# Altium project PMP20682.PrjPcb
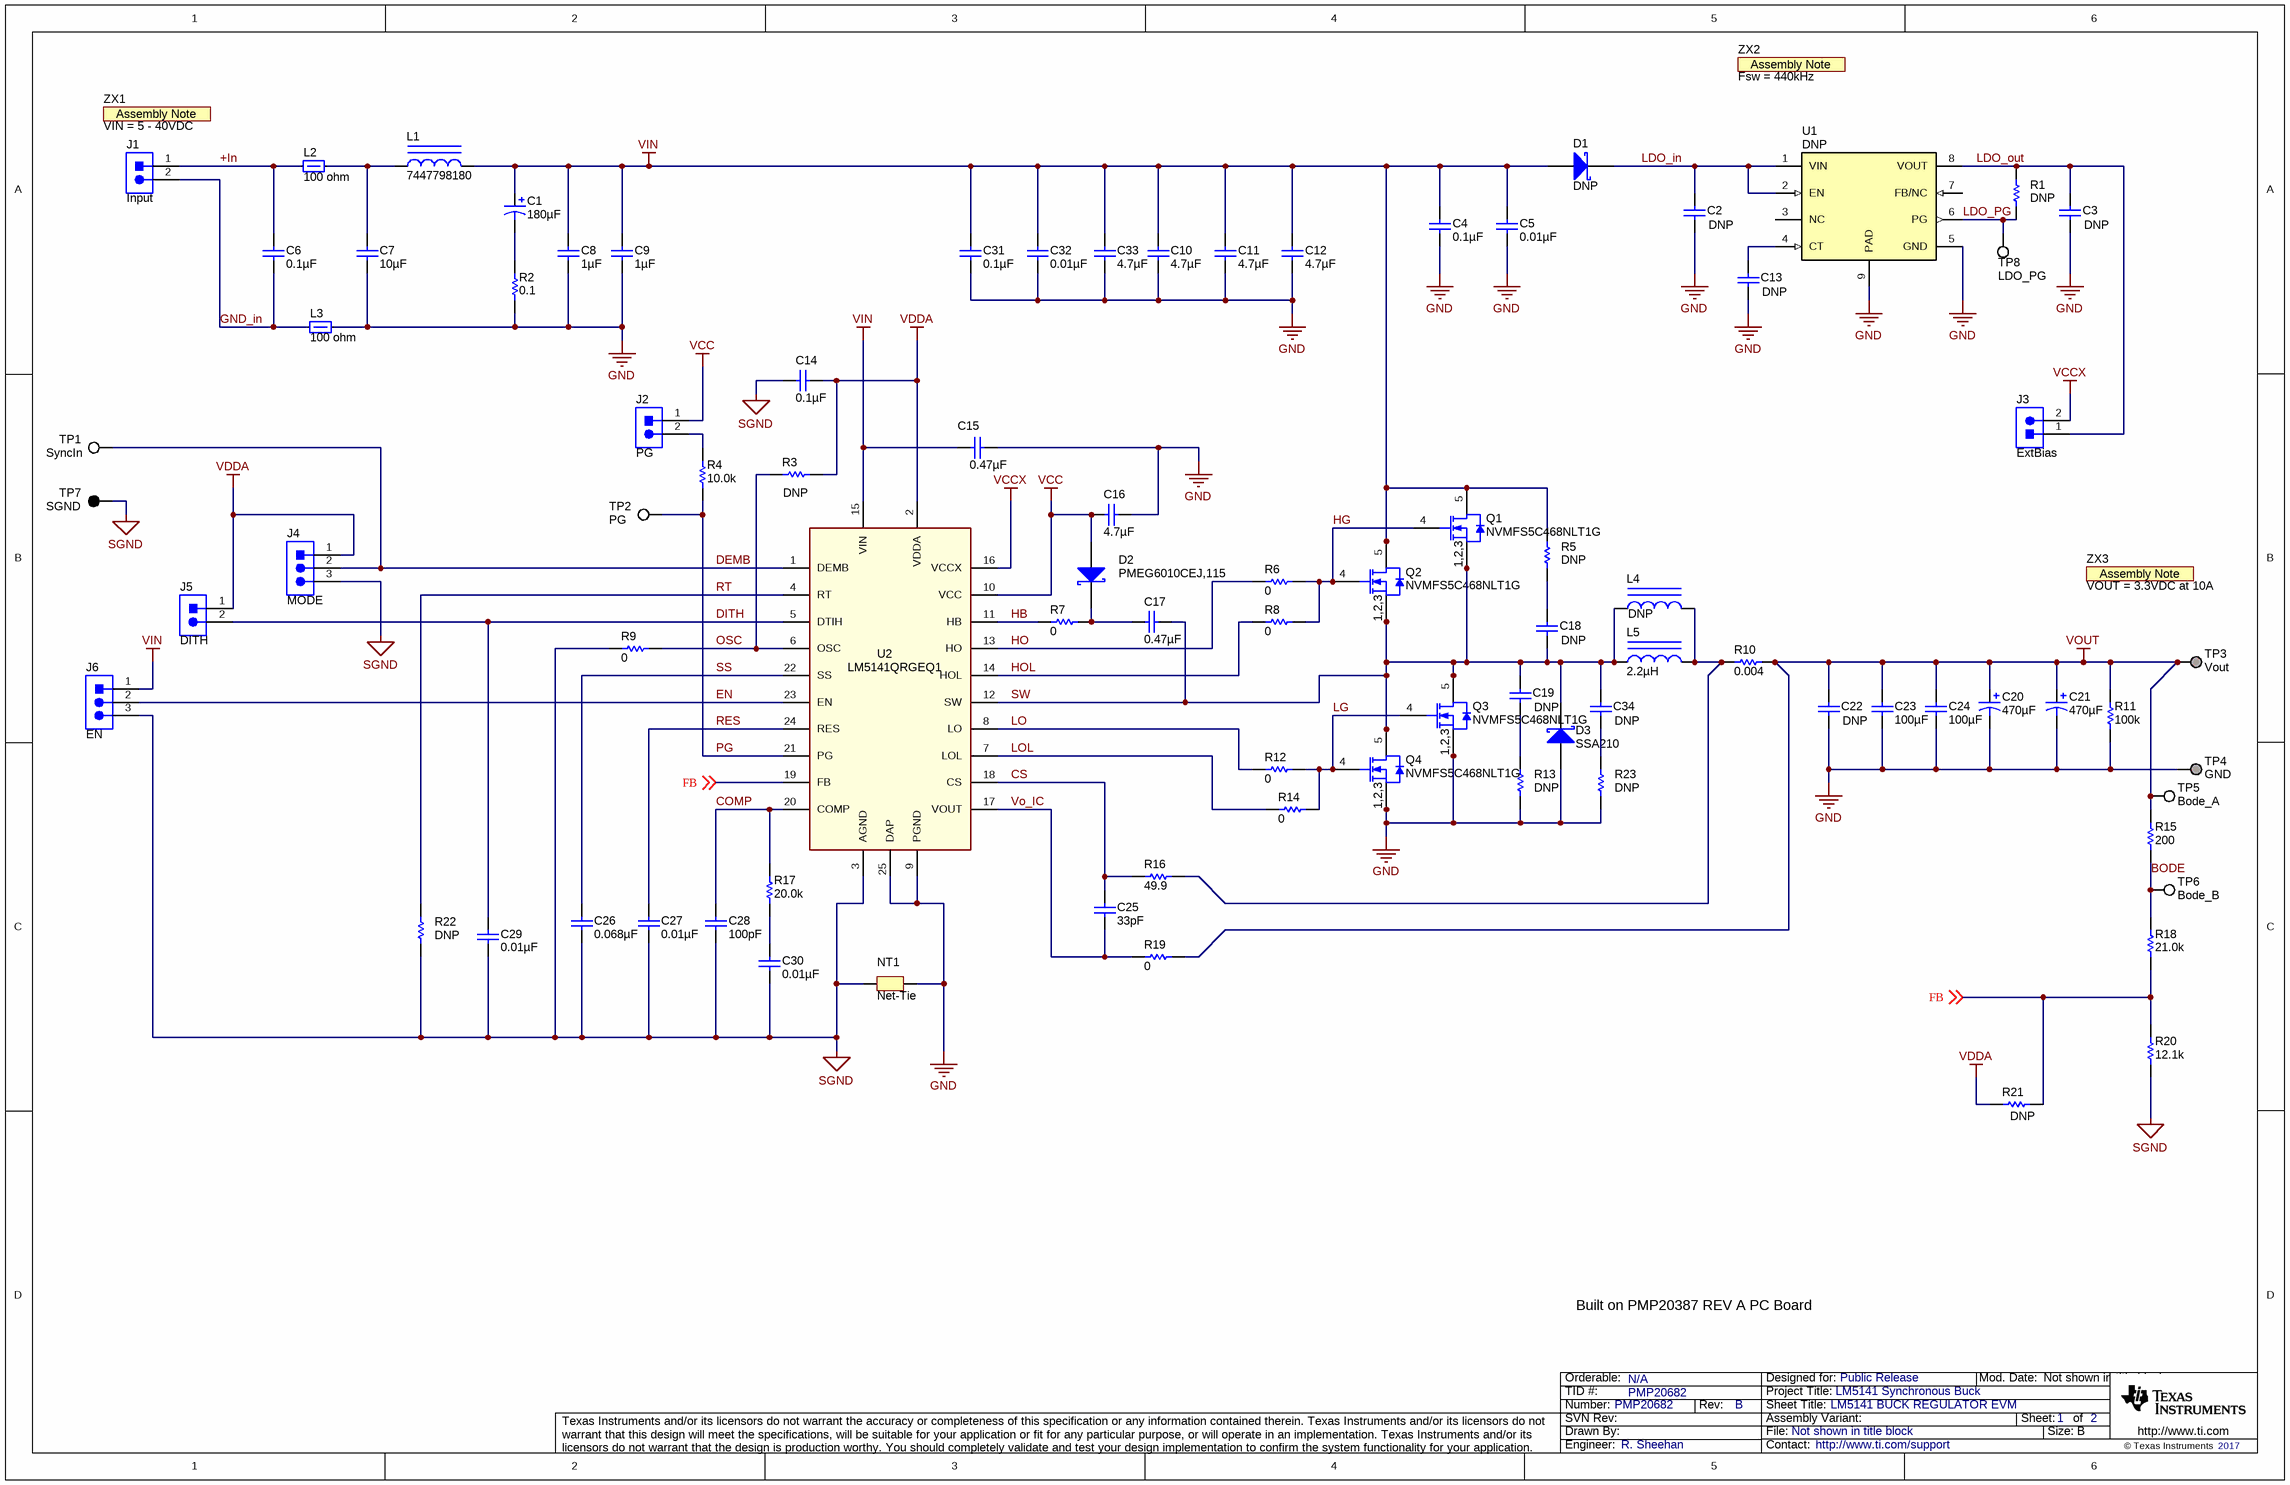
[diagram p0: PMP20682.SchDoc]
CopyrightYear: 2017; EVM_Orderable: N/A; PCB_Layout: H. Kasparian; PCB_Rev: A; PRJ_Customer: Public Release; PRJ_Engineer: R. Sheehan; PRJ_Number: PMP20682; PRJ_Title: LM5141 Synchronous Buck; SCH_Rev: B; TechSupport: http://www.ti.com/support; TID: PMP20682
2 sheets, 120 parts. Net scope: global (net labels, ports and power ports of the same name join across sheets).
Board file: PMP20387.PcbDoc
Sheets:
  PMP20682.SchDoc
  PMP20682-HW.SchDoc

## Sheet PMP20682.SchDoc: LM5141 BUCK REGULATOR EVM
size 431 x 279 mm; Date: Not shown in title block; ApprovedBy: Not shown in title block; CheckedBy: Not shown in title block; Author: Not shown in title block; CompanyName: Not shown in title block; Engineer: Not shown in title block; Organization: Not shown in title block; Address1: Not shown in title block; Address2: Not shown in title block; Address3: Not shown in title block; Address4: Not shown in title block; DocumentNumber: 1; Revision: Use project parameter SCH_Rev; SheetNumber: 1; SheetTotal: 2; PageSetup: Record=PageOptions¦CenterHorizontal=True¦CenterVertical=True¦PrintScale=0.96¦XCorrection=1.00¦YCorrection=1.00¦PrintKind=0¦BorderSize=5000000¦LeftOffset=0¦BottomOffset=0¦Orientation=2¦PaperLength=1000¦PaperWidth=1000¦Scale=100¦PaperSource=15¦PrintQuality=-3¦MediaType=1¦DitherType=10¦PrintScaleMode=1¦PaperKind=11x17¦PaperIndex=17

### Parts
C1  ValueDisplayed: 180µF  [UCZ_1250x1350]  (hidden comment: UCZ1J181MNQ1MS)
C2  DNP  [1206L]
C3  DNP  [0603]
C4  ValueDisplayed: 0.1µF  [0805_HV]  (hidden comment: C0805C104K1RACTU)
C5  ValueDisplayed: 0.01µF  [0603]  (hidden comment: C1608X7R2A103M)
C6  ValueDisplayed: 0.1µF  [0805_HV]  (hidden comment: C0805C104K1RACTU)
C7  ValueDisplayed: 10µF  [1210_280]  (hidden comment: C3225X7R1H106M250AC)
C8  ValueDisplayed: 1µF  [1206L]  (hidden comment: C3216X7R2A105M160AA)
C9  ValueDisplayed: 1µF  [1206L]  (hidden comment: C3216X7R2A105M160AA)
C10  ValueDisplayed: 4.7µF  [1206_190]  (hidden comment: UMK316AB7475KL-T)
C11  ValueDisplayed: 4.7µF  [1206_190]  (hidden comment: UMK316AB7475KL-T)
C12  ValueDisplayed: 4.7µF  [1206_190]  (hidden comment: UMK316AB7475KL-T)
C13  DNP  [0603]
C14  ValueDisplayed: 0.1µF  [0603]  (hidden comment: C0603C104K5RACTU)
C15  ValueDisplayed: 0.47µF  [0805L]  (hidden comment: GRM21BR72A474KA73L)
C16  ValueDisplayed: 4.7µF  [0603]  (hidden comment: GRM188R61C475KAAJ)
C17  ValueDisplayed: 0.47µF  [0603]  (hidden comment: CGA3E3X7R1H474K080AB)
C18  DNP  [0603]
C19  DNP  [0603]
C20  ValueDisplayed: 470µF  [CAPSMT_62_JC0]  (hidden comment: 16SVPE470M)
C21  ValueDisplayed: 470µF  [CAPSMT_62_JC0]  (hidden comment: 16SVPE470M)
C22  DNP  [0603]
C23  ValueDisplayed: 100µF  [1210_280]  (hidden comment: LMK325ABJ107MMHT)
C24  ValueDisplayed: 100µF  [1210_280]  (hidden comment: LMK325ABJ107MMHT)
C25  ValueDisplayed: 33pF  [0603]  (hidden comment: 06035A330JAT2A)
C26  ValueDisplayed: 0.068µF  [0603]  (hidden comment: GRM188R71E683KA01D)
C27  ValueDisplayed: 0.01µF  [0603]  (hidden comment: C1608X7R2A103M)
C28  ValueDisplayed: 100pF  [0603]  (hidden comment: GRM1885C1H101JA01D)
C29  ValueDisplayed: 0.01µF  [0603]  (hidden comment: C1608X7R2A103M)
C30  ValueDisplayed: 0.01µF  [0603]  (hidden comment: GRM188R71E103KA01D)
C31  ValueDisplayed: 0.1µF  [0805_HV]  (hidden comment: C0805C104K1RACTU)
C32  ValueDisplayed: 0.01µF  [0603]  (hidden comment: C1608X7R2A103M)
C33  ValueDisplayed: 4.7µF  [1206_190]  (hidden comment: UMK316AB7475KL-T)
C34  DNP  [0603]
D1  DNP  [SOD-323F]
D2  PMEG6010CEJ,115  [SOD-323F]
D3  SSA210  [SMA]
J1  Input  [Phoenix_1729018]
J2  PG  [WURTH_61300211121]
J3  ExtBias  [WURTH_61300211121]
J4  MODE  [WURTH_61300311121]
J5  DITH  [WURTH_61300211121]
J6  EN  [WURTH_61300311121]
L1  7447798180  [WE-PDF_1064]
L2  value 100 ohm  [WE-MPSB_2220_1800]  (hidden comment: 74279224101)
L3  value 100 ohm  [WE-MPSB_2220_1800]  (hidden comment: 74279224101)
L4  DNP  [IHLP-4040DZ]
L5  ValueDisplayed: 2.2µH  [XAL1060]  (hidden comment: XAL1060-222MEB)
NT1  Net-Tie  [Net-Tie_10mil]  (net tie, no BOM)
Q1  NVMFS5C468NLT1G  [TRANS_DFN5]
Q2  NVMFS5C468NLT1G  [TRANS_DFN5]
Q3  NVMFS5C468NLT1G  [TRANS_DFN5]
Q4  NVMFS5C468NLT1G  [TRANS_DFN5]
R1  DNP  [0603]
R2  ValueDisplayed: 0.1  [2010]  (hidden comment: WSL2010R1000FEA)
R3  DNP  [0603]
R4  ValueDisplayed: 10.0k  [0603]  (hidden comment: CRCW060310K0FKEA)
R5  DNP  [1206]
R6  ValueDisplayed: 0  [0603S]  (hidden comment: CRCW06030000Z0EA)
R7  ValueDisplayed: 0  [0603S]  (hidden comment: CRCW06030000Z0EA)
R8  ValueDisplayed: 0  [0603S]  (hidden comment: CRCW06030000Z0EA)
R9  ValueDisplayed: 0  [0603]  (hidden comment: CRCW06030000Z0EA)
R10  ValueDisplayed: 0.004  [2512_WIDE]  (hidden comment: KRL6432E-M-R004-F-T1)
R11  ValueDisplayed: 100k  [0603]  (hidden comment: CRCW0603100KFKEA)
R12  ValueDisplayed: 0  [0603S]  (hidden comment: CRCW06030000Z0EA)
R13  DNP  [1206]
R14  ValueDisplayed: 0  [0603S]  (hidden comment: CRCW06030000Z0EA)
R15  ValueDisplayed: 200  [0603]  (hidden comment: CRCW0603200RFKEA)
R16  ValueDisplayed: 49.9  [0603]  (hidden comment: CRCW060349R9FKEA)
R17  ValueDisplayed: 20.0k  [0603]  (hidden comment: CRCW060320K0FKEA)
R18  ValueDisplayed: 21.0k  [0603]  (hidden comment: CRCW060321K0FKEA)
R19  ValueDisplayed: 0  [0603]  (hidden comment: CRCW06030000Z0EA)
R20  ValueDisplayed: 12.1k  [0603]  (hidden comment: CRCW060312K1FKEA)
R21  DNP  [0603]
R22  DNP  [0603]
R23  DNP  [1206]
TP1  SyncIn  [Keystone5012]
TP2  PG  [Keystone5002]
TP3  Vout  [Keystone1598-2]
TP4  GND  [Keystone1598-2]
TP5  Bode_A  [Keystone5012]
TP6  Bode_B  [Keystone5012]
TP7  SGND  [Keystone5011]
TP8  LDO_PG  [Keystone5012]
U1  DNP  [DGN0008D_N]
U2  LM5141QRGEQ1  [RGE0024H]
ZX1  VIN = 5 - 40VDC  [AssemblyNote]  (no BOM)
ZX2  Fsw = 440kHz  [AssemblyNote]  (no BOM)
ZX3  VOUT = 3.3VDC at 10A  [AssemblyNote]  (no BOM)

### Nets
GND: C2.2 C3.2 C4.2 C5.2 C7.2 C8.2 C9.2 C10.2 C11.2 C12.2 C13.2 C15.1 C16.1 C20.2(-) C21.2(-) C22.2 C23.2 C24.2 C31.2 C32.2 C33.2 D3.2(A) L3.2 NT1.2 Q3.1(S) Q3.2(S) Q3.3(S) Q4.1(S) Q4.2(S) Q4.3(S) R2.1 R11.1 R13.1 R23.1 TP4.1 U1.5(GND) U1.9(PAD) U2.9(PGND) U2.25(DAP)
SGND: C14.1 C26.2 C27.2 C28.2 C29.2 C30.2 J4.3 J6.3 NT1.1 R9.2 R20.1 R22.1 TP7.1 U2.3(AGND)
VCC: C16.2 D2.2(A) J2.1 U2.10(VCC)
VCCX: J3.2 U2.16(VCCX)
VDDA: C14.2 J4.1 J5.1 R3.1 R21.1 U2.2(VDDA)
VIN: C1.1(+) C4.1 C5.1 C8.1 C9.1 C10.1 C11.1 C12.1 C15.2 C31.1 C32.1 C33.1 D1.2(A) J6.1 L1.2 Q1.5(D) Q1.6(D) Q2.5(D) Q2.6(D) R5.2 U2.15(VIN)
VOUT: C20.1(+) C21.1(+) C22.1 C23.1 C24.1 R10.2 R11.2 R15.2 R19.2 TP3.1 TP5.1
+In: C6.1 J1.1 L2.1
BODE: R15.1 R18.2 TP6.1
COMP: C28.1 R17.2 U2.20(COMP)
CS: C25.2 R16.1 U2.18(CS)
DEMB: J4.2 TP1.1 U2.1(DEMB)
DITH: C29.1 J5.2 U2.5(DTIH)
EN: J6.2 U2.23(EN)
FB: R18.1 R20.2 R21.2 U2.19(FB) ; off-sheet FB
GND_in: C6.2 J1.2 L3.1
HB: R7.1 U2.11(HB)
HG: Q1.4(G) Q2.4(G) R6.2 R8.1
HO: R6.1 U2.13(HO)
HOL: R8.2 U2.14(HOL)
LDO_in: C2.1 D1.1(K) U1.1(VIN) U1.2(EN)
LDO_out: C3.1 J3.1 R1.2 U1.8(VOUT)
LDO_PG: R1.1 TP8.1 U1.6(PG)
LG: Q3.4(G) Q4.4(G) R12.2 R14.1
LO: R12.1 U2.8(LO)
LOL: R14.2 U2.7(LOL)
OSC: R3.2 R9.1 U2.6(OSC)
PG: R4.2 TP2.1 U2.21(PG)
RES: C27.1 U2.24(RES)
RT: R22.2 U2.4(RT)
SS: C26.1 U2.22(SS)
SW: C17.2 C18.2 C19.1 C34.1 D3.1(K) L4.1 L5.1 Q1.1(S) Q1.2(S) Q1.3(S) Q2.1(S) Q2.2(S) Q2.3(S) Q3.5(D) Q3.6(D) Q4.5(D) Q4.6(D) U2.12(SW)
Vo_IC: C25.1 R19.1 U2.17(VOUT)
NetC1_2: C1.2(-) R2.2
NetC7_1: C7.1 L1.1 L2.2
NetC13_1: C13.1 U1.4(CT)
NetC17_1: C17.1 D2.1(K) R7.2
NetC18_1: C18.1 R5.1
NetC19_2: C19.2 R13.2
NetC30_1: C30.1 R17.1
NetC34_2: C34.2 R23.2
NetJ2_2: J2.2 R4.1
NetL4_2: L4.2 L5.2 R10.1 R16.2

Not connected (* = marked no-connect by the designer): U1 3(NC) 7(FB/NC)

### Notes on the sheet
- Built on PMP20387 REV A PC Board

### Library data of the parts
C1 = UCZ1J181MNQ1MS: CAP, AL, 180 µF, 63 V, +/- 20%, 0.2 ohm, AEC-Q200 Grade 1, SMD; Manufacturer: Nichicon; Polarized: Y; CompType: Capacitor; Value: 180uF; U/M: EA; Cap_F: 0.00018; Tolerance_%: 20; Value1: 0.2 ohm; VDC_V: 63; Value2: 63V; ESR_ohm: 0.2; IRMS_A: 1; TaMin_C: -40; TaMax_C: 125; Cap_Case: 12.5x13.5mm; AEC Category: Q200
C2 = C3216X7R2A105M160AA: CAP, CERM, 1 µF, 100 V, +/- 20%, X7R, 1206; Manufacturer: TDK; Polarized: N; CompType: Capacitor; Value: 1uF; ValueDisplayed: 1µF; U/M: EA; Cap_F: 0.000001; Tolerance_%: 20; Value1: Unknown; VDC_V: 100; Value2: 100V; TaMin_C: -55; TaMax_C: 125; Cap_Case: 1206
C3 = GRM188Z71C225KE43: CAP, CERM, 2.2 µF, 16 V, +/- 10%, X7R, 0603; Manufacturer: MuRata; Polarized: N; CompType: Capacitor; Value: 2.2uF; ValueDisplayed: 2.2µF; U/M: EA; Cap_F: 0.0000022; Tolerance_%: 10; Value1: Unknown; VDC_V: 16; Value2: 16V; TaMin_C: -55; TaMax_C: 125; SizeArea_mm2: 1.28; SizeAreaWB_mm2: 4.68; SizeX_mm: 1.6; SizeY_mm: 0.8; SizeZ_mm: 1; AEC Category: Q200
C4 C6 C31 = C0805C104K1RACTU: CAP, CERM, 0.1 µF, 100 V, +/- 10%, X7R, 0805; Manufacturer: Kemet; Polarized: N; CompType: Capacitor; Value: 0.1uF; U/M: EA; Cap_F: 0.0000001; Tolerance_%: 10; ESR_ohm: 0.064; Value1: 0.064 ohm; VDC_V: 100; Value2: 100V; IRMS_A: 1.64; TaMin_C: -55; TaMax_C: 125; Cap_Case: 0805
C5 C27 C29 C32 = C1608X7R2A103M: CAP, CERM, 0.01 µF, 100 V, +/- 20%, X7R, 0603; Manufacturer: TDK; Polarized: N; CompType: Capacitor; Value: 0.01uF; U/M: EA; Cap_F: 0.00000001; Tolerance_%: 20; ESR_ohm: 0.0661; Value1: 0.0661 ohm; VDC_V: 100; Value2: 100V; TaMin_C: -55; TaMax_C: 125
C7 = C3225X7R1H106M250AC: CAP, CERM, 10 µF, 50 V, +/- 20%, X7R, 1210; Manufacturer: TDK; Polarized: N; CompType: Capacitor; Value: 10uF; U/M: EA; Cap_F: 0.00001; Tolerance_%: 20; Value1: Unknown; VDC_V: 50; Value2: 50V; TaMin_C: -55; TaMax_C: 125; Cap_Case: 1210
C8 C9 = C3216X7R2A105M160AA: CAP, CERM, 1 µF, 100 V, +/- 20%, X7R, 1206; Manufacturer: TDK; Polarized: N; CompType: Capacitor; Value: 1uF; U/M: EA; Cap_F: 0.000001; Tolerance_%: 20; Value1: Unknown; VDC_V: 100; Value2: 100V; TaMin_C: -55; TaMax_C: 125; Cap_Case: 1206
C10-C12 C33 = UMK316AB7475KL-T: CAP, CERM, 4.7 µF, 50 V, +/- 10%, X7R, 1206_190; Manufacturer: Taiyo Yuden; Polarized: N; CompType: Capacitor; Value: 4.7uF; U/M: EA; Cap_F: 0.0000047; Tolerance_%: 10; Value1: Unknown; VDC_V: 50; Value2: 50V; TaMin_C: -55; TaMax_C: 125; Cap_Case: 1206; SizeArea_mm2: 5.12; SizeAreaWB_mm2: 10.92; SizeX_mm: 3.2; SizeY_mm: 1.6; SizeZ_mm: 1.9; AEC Category: Q200
C13 = GRM188R71E102KA01D: CAP, CERM, 1000 pF, 25 V, +/- 10%, X7R, 0603; Manufacturer: MuRata; Polarized: N; CompType: Capacitor; Value: 1000pF; U/M: EA; Cap_F: 0.000000001; Tolerance_%: 10; Value1: Unknown; VDC_V: 25; Value2: 25V; TaMin_C: -55; TaMax_C: 125; SizeArea_mm2: 1.28; SizeAreaWB_mm2: 4.68; SizeX_mm: 1.6; SizeY_mm: 0.8; SizeZ_mm: 1; AEC Category: Q200
C14 = C0603C104K5RACTU: CAP, CERM, 0.1 µF, 50 V, +/- 10%, X7R, 0603; Manufacturer: Kemet; Polarized: N; CompType: Capacitor; Value: 0.1uF; U/M: EA; Cap_F: 0.0000001; Tolerance_%: 10; Value1: Unknown; VDC_V: 50; Value2: 50V; TaMin_C: -55; TaMax_C: 125
C15 = GRM21BR72A474KA73L: CAP, CERM, 0.47 µF, 100 V, +/- 10%, X7R, 0805; Manufacturer: MuRata; Polarized: N; CompType: Capacitor; Value: 0.47uF; U/M: EA; Cap_F: 0.00000047; Tolerance_%: 10; Value1: Unknown; VDC_V: 100; Value2: 100V; TaMin_C: -55; TaMax_C: 125; Cap_Case: 0805
C16 = GRM188R61C475KAAJ: CAP, CERM, 4.7 µF, 16 V, +/- 10%, X5R, 0603; Manufacturer: MuRata; Polarized: N; CompType: Capacitor; Value: 4.7uF; U/M: EA; Cap_F: 0.0000047; Tolerance_%: 10; Value1: Unknown; VDC_V: 16; Value2: 16V; TaMin_C: -55; TaMax_C: 85
C17 = CGA3E3X7R1H474K080AB: CAP, CERM, 0.47 µF, 50 V, +/- 10%, X7R, AEC-Q200 Grade 1, 0603; Manufacturer: TDK; Polarized: N; CompType: Capacitor; Value: 0.47uF; U/M: EA; Cap_F: 0.00000047; Tolerance_%: 10; ESR_ohm: 0.01064; Value1: 0.01064 ohm; VDC_V: 50; Value2: 50V; IRMS_A: 1.59966; TaMin_C: -55; TaMax_C: 125; SizeArea_mm2: 1.28; SizeAreaWB_mm2: 4.68; SizeX_mm: 1.6; SizeY_mm: 0.8; SizeZ_mm: 1; AEC Category: Q200; AEC Qualified: Y
C18 C19 C34 = GRM1885C2A102JA01D: CAP, CERM, 1000 pF, 100 V, +/- 5%, C0G/NP0, 0603; Manufacturer: MuRata; Polarized: N; CompType: Capacitor; Value: 1000pF; U/M: EA; Cap_F: 0.000000001; Tolerance_%: 5; Value1: Unknown; VDC_V: 100; Value2: 100V; TaMin_C: -55; TaMax_C: 125
C20 C21 = 16SVPE470M: CAP, Aluminum Polymer, 470 µF, 16 V, +/- 20%, 0.01 ohm, JC0 SMD; Manufacturer: Panasonic; Polarized: Y; CompType: Capacitor; Value: 470uF; U/M: EA; Cap_F: 0.00047; Tolerance_%: 20; VDC_V: 16; Value2: 16V; ESR_ohm: 0.01; IRMS_A: 6.1; TaMin_C: -55; TaMax_C: 105; AEC Category: Q200; SizeAreaWB_mm2: 156.25; SizeArea_mm2: 110.25; SizeX_mm: 10.5; SizeZ_mm: 12.5
C22 = C0603C104K5RACTU: CAP, CERM, 0.1 µF, 50 V, +/- 10%, X7R, 0603; Manufacturer: Kemet; Polarized: N; CompType: Capacitor; Value: 0.1uF; ValueDisplayed: 0.1µF; U/M: EA; Cap_F: 0.0000001; Tolerance_%: 10; Value1: Unknown; VDC_V: 50; Value2: 50V; TaMin_C: -55; TaMax_C: 125
C23 C24 = LMK325ABJ107MMHT: CAP, CERM, 100 µF, 10 V, +/- 20%, X5R, AEC-Q200 Grade 3, 1210; Manufacturer: Taiyo Yuden; Polarized: N; CompType: Capacitor; Value: 100uF; U/M: EA; Cap_F: 0.0001; Tolerance_%: 20; Value1: Unknown; VDC_V: 10; Value2: 10V; TaMin_C: -55; TaMax_C: 85; Cap_Case: 1210; SizeArea_mm2: 8; SizeAreaWB_mm2: 14.7; SizeX_mm: 3.2; SizeY_mm: 2.5; SizeZ_mm: 2.8; AEC Category: Q200; AEC Qualified: Y; AEC Grade: 3
C25 = 06035A330JAT2A: CAP, CERM, 33 pF, 50 V, +/- 5%, C0G/NP0, 0603; Manufacturer: AVX; Polarized: N; CompType: Capacitor; Value: 33pF; U/M: EA; Cap_F: 0.000000000033; Tolerance_%: 5; ESR_ohm: 0.209; Value1: 0.209 ohm; VDC_V: 50; Value2: 50V; TaMin_C: -55; TaMax_C: 125
C26 = GRM188R71E683KA01D: CAP, CERM, 0.068 µF, 25 V, +/- 10%, X7R, 0603; Manufacturer: MuRata; Polarized: N; CompType: Capacitor; Value: 0.068uF; U/M: EA; Cap_F: 0.000000068; Tolerance_%: 10; Value1: Unknown; VDC_V: 25; Value2: 25V; TaMin_C: -55; TaMax_C: 125
C28 = GRM1885C1H101JA01D: CAP, CERM, 100 pF, 50 V, +/- 5%, C0G/NP0, 0603; Manufacturer: MuRata; Polarized: N; CompType: Capacitor; Value: 100pF; U/M: EA; Cap_F: 0.0000000001; Tolerance_%: 5; Value1: Unknown; VDC_V: 50; Value2: 50V; TaMin_C: -55; TaMax_C: 125; SizeArea_mm2: 1.28; SizeAreaWB_mm2: 4.68; SizeX_mm: 1.6; SizeY_mm: 0.8; SizeZ_mm: 1; AEC Category: Q200
C30 = GRM188R71E103KA01D: CAP, CERM, 0.01 µF, 25 V, +/- 10%, X7R, 0603; Manufacturer: MuRata; Polarized: N; CompType: Capacitor; Value: 0.01uF; U/M: EA; Cap_F: 0.00000001; Tolerance_%: 10; Value1: Unknown; VDC_V: 25; Value2: 25V; TaMin_C: -55; TaMax_C: 125; SizeArea_mm2: 1.28; SizeAreaWB_mm2: 4.68; SizeX_mm: 1.6; SizeY_mm: 0.8; SizeZ_mm: 1; AEC Category: Q200
D1 D2 = PMEG6010CEJ,115: Diode, Schottky, 60 V, 1 A, SOD-323F; Manufacturer: NXP Semiconductor; U/M: EA; Vf_V: 0.66; Value: 60V; Value1: 1A; Value2: 0.66V; Io_A: 1; Vr_V: 60; TJmax_C: 150
D3 = SSA210: Diode, Schottky, 100 V, 2 A, AEC-Q101, SMA; Manufacturer: Fairchild Semiconductor; U/M: EA; Vf_V: 0.8; Value: 100V; Value1: 2A; Value2: 0.8V; Io_A: 2; Vr_V: 100; TJmax_C: 175; SizeAreaWB_mm2: 37.3428; SizeArea_mm2: 16.3228; SizeX_mm: 5.59; SizeY_mm: 2.92; SizeZ_mm: 2.87; AEC Category: Q101; AEC Qualified: Y
J1 = 1729018: TERM BLOCK 2POS 5mm, TH; Manufacturer: Phoenix Contact; SymbolCreator: a0412235; CompType: Header; U/M: EA
J2 J3 J5 = 61300211121: Header, 2.54 mm, 2x1, Gold, TH; Manufacturer: Wurth Elektronik; SymbolCreator: a0412235
J4 J6 = 61300311121: Header, 2.54 mm, 3x1, Gold, TH; Manufacturer: Wurth Elektronik; SymbolCreator: a0799628
L1 = 7447798180: Inductor, Shielded, Metal Composite, 1.8 µH, 12.8 A, 0.0038 ohm, SMD; Manufacturer: Wurth Elektronik; Value: 1.8uH; Ind_H: 1.8E-6; ValueDisplayed: 1.8µH; Imax_A: 12.8; Irms: 14.5A @ 40C rise; Isat: 12.8A @ 10% inductance drop; DCR_ohm: 0.0038; Value2: 12.8A
L2 L3 = 74279224101: Ferrite Bead, 100 ohm @ 100 MHz, 7 A, 2220 (H=1.8mm); Manufacturer: Wurth Elektronik; Imax_A: 7; DCR_ohm: 0.005; Value1: 0.005 ohm; Value2: 7A; ZTyp@100MHz_Ohm: 100
L4 = IHLP4040DZER2R0M11: Inductor, Shielded Drum Core, Powdered Iron, 2 µH, 14 A, 0.0058 ohm, SMD; Manufacturer: Vishay-Dale; Value: 2uH; ValueDisplayed: 2µH; Ind_H: 2.0E-6; Imax_A: 14; Irms: 16A @ 40C rise; Isat: 14A @ 20% inductance drop; DCR_ohm: 0.0058; Value2: 14A; AEC Category: Q200; AEC Qualified: N
L5 = XAL1060-222MEB: Inductor, Shielded, Composite, 2.2 µH, 20 A, 0.0045 ohm, AEC-Q200 Grade 1, SMD; Manufacturer: Coilcraft; Value: 2.2uH; Ind_H: 2.2E-6; Imax_A: 20; Irms: 20A @ 40C rise; Isat: 32A @ 30% inductance drop; DCR_ohm: 0.0045; Value2: 20A; AEC Category: Q200; AEC Qualified: Y; AEC Grade: 1; SizeAreaWB_mm2: 159.6; SizeArea_mm2: 113; SizeX_mm: 11.3; SizeY_mm: 10; SizeZ_mm: 6
NT1 = Net-Tie: Single point connection between nets.; SymbolCreator: codlsc
Q1-Q4 = NVMFS5C468NL: MOSFET, N-CH, 40 V, 37 A, AEC-Q101, DFN5 5x6mm; Manufacturer: ON Semiconductor; Alternate Manufacturer: None; U/M: EA; VdsMax_V: 40; ChType: N; Value: 40V; Value1: 0.0145 ohm; Rdson45_ohm: 0.0145; Value2: 4.5 nC; QgTyp_nC: 4.5; Vgs_V: 20; IdsMax_A: 27; SizeAreaWB_mm2: 58.2725; SizeArea_mm2: 31.6725; SizeX_mm: 5.15; SizeY_mm: 6.15; SizeZ_mm: 1; AEC Category: Q101; AEC Qualified: Y
R1 R4 = CRCW060310K0FKEA: RES, 10.0 k, 1%, 0.1 W, 0603; Manufacturer: Vishay-Dale; CompType: Resistor; Value: 10.0k; Res_ohm: 10000; Value_Code: 10k0; Tolerance_%: 1; Power_W: 0.1; Value2: 0.1W; VDC_V: 75; TempCo: 100 ppm/C; EIA_Code: E96; U/M: EA
R2 = WSL2010R1000FEA: RES, 0.1, 1%, 0.5 W, 2010; Manufacturer: Vishay-Dale; CompType: Resistor; Value: 0.1; Value_Code: R100; Tolerance_%: 1; Power_W: 0.5; Value2: 0.5W; TempCo: 75 ppm/C; EIA_Code: E96; U/M: EA; SizeArea_mm2: 12.5; SizeX_mm: 5; SizeY_mm: 2.5; SizeZ_mm: 1.66; AEC Category: Q200
R3 R8 R9 R19 = CRCW06030000Z0EA: RES, 0, 5%, 0.1 W, 0603; Manufacturer: Vishay-Dale; CompType: Resistor; Value: 0; Value_Code: 0000; Tolerance_%: 5; Power_W: 0.1; Value2: 0.1W; VDC_V: 75; TempCo: 200 ppm/C; EIA_Code: E24; U/M: EA
R5 R13 R23 = CRM1206-JW-1R0ELF: RES, 1.0, 5%, 0.5 W, 1206; Manufacturer: Bourns; CompType: Resistor; Value: 1.0; Res_ohm: 1; Value_Code: 1R00; Tolerance_%: 5; Power_W: 0.5; Value2: 0.5W; TempCo: 150 ppm/C; EIA_Code: E24; U/M: EA
R6 R7 R12 R14 = CRCW06030000Z0EA: RES, 0, 5%, 0.1 W, 0603; Manufacturer: Vishay-Dale; CompType: Resistor; Value: 0; Value_Code: 0000; Tolerance_%: 5; Power_W: 0.1; Value2: 0.1W; VDC_V: 75; TempCo: 200 ppm/C; EIA_Code: E24; U/M: EA; SizeArea_mm2: 1.28; SizeX_mm: 1.6; SizeY_mm: 0.8; SizeZ_mm: 1; AEC Category: Q200
R10 = KRL6432E-M-R007-F-T1: RES, 0.004, 1%, 3 W, 2512 WIDE; Manufacturer: Susumu Co Ltd; CompType: Resistor; Value: 0.004; U/M: EA; Value_Code: 4L000; Tolerance_%: 1; Power_W: 3; Value2: 3W; TempCo: 50 ppm/C; SizeArea_mm2: 20.16; SizeAreaWB_mm2: 43.16; SizeX_mm: 3.2; SizeY_mm: 6.3; SizeZ_mm: 0.7; EIA_Code: E96; AEC Category: Q200
R11 = CRCW0603100KFKEA: RES, 100 k, 1%, 0.1 W, 0603; Manufacturer: Vishay-Dale; CompType: Resistor; Value: 100k; Res_ohm: 100000; Tolerance_%: 1; Power_W: 0.1; Value2: 0.1W; VDC_V: 75; TempCo: 100 ppm/C; EIA_Code: E96; U/M: EA
R15 = CRCW0603200RFKEA: RES, 200, 1%, 0.1 W, 0603; Manufacturer: Vishay-Dale; CompType: Resistor; Value: 200; Value_Code: 200R; Tolerance_%: 1; Power_W: 0.1; Value2: 0.1W; VDC_V: 75; TempCo: 100 ppm/C; EIA_Code: E96; U/M: EA; SizeArea_mm2: 1.28; SizeX_mm: 1.6; SizeY_mm: 0.8; AEC Category: Q200
R16 = CRCW060349R9FKEA: RES, 49.9, 1%, 0.1 W, 0603; Manufacturer: Vishay-Dale; CompType: Resistor; Value: 49.9; Value_Code: 49R9; Tolerance_%: 1; Power_W: 0.1; Value2: 0.1W; VDC_V: 75; TempCo: 100 ppm/C; EIA_Code: E96; U/M: EA
R17 = CRCW060320K0FKEA: RES, 20.0 k, 1%, 0.1 W, 0603; Manufacturer: Vishay-Dale; CompType: Resistor; Value: 20.0k; Res_ohm: 20000; Value_Code: 20k0; Tolerance_%: 1; Power_W: 0.1; Value2: 0.1W; VDC_V: 75; TempCo: 100 ppm/C; EIA_Code: E96; U/M: EA; SizeArea_mm2: 1.28; SizeX_mm: 1.6; SizeY_mm: 0.8; AEC Category: Q200
R18 = CRCW060321K0FKEA: RES, 21.0 k, 1%, 0.1 W, 0603; Manufacturer: Vishay-Dale; CompType: Resistor; Value: 21.0k; Res_ohm: 21000; Value_Code: 21k0; Tolerance_%: 1; Power_W: 0.1; Value2: 0.1W; VDC_V: 75; TempCo: 100 ppm/C; EIA_Code: E96; U/M: EA; AEC Category: Q200; SizeArea_mm2: 1.28; SizeX_mm: 1.6; SizeY_mm: 0.8
R20 = CRCW060312K1FKEA: RES, 12.1 k, 1%, 0.1 W, 0603; Manufacturer: Vishay-Dale; CompType: Resistor; Value: 12.1k; Res_ohm: 12100; Value_Code: 12k1; Tolerance_%: 1; Power_W: 0.1; Value2: 0.1W; VDC_V: 75; TempCo: 100 ppm/C; EIA_Code: E96; U/M: EA; SizeArea_mm2: 1.28; SizeX_mm: 1.6; SizeY_mm: 0.8; AEC Category: Q200
R21 = CRCW06030000Z0EA: RES, 0, 5%, 0.1 W, 0603; Manufacturer: Vishay-Dale; CompType: Resistor; Value: 0; Value_Code: 0000; Tolerance_%: 5; Power_W: 0.1; Value2: 0.1W; VDC_V: 75; TempCo: 200 ppm/C; SizeArea_mm2: 1.28; SizeX_mm: 1.6; SizeY_mm: 0.8; SizeZ_mm: 1; EIA_Code: E24; U/M: EA; AEC Category: Q200
R22 = CRCW060349K9FKEA: RES, 49.9 k, 1%, 0.1 W, 0603; Manufacturer: Vishay-Dale; CompType: Resistor; Value: 49.9k; Res_ohm: 49900; Value_Code: 49k9; Tolerance_%: 1; Power_W: 0.1; Value2: 0.1W; VDC_V: 75; TempCo: 100 ppm/C; SizeArea_mm2: 1.28; SizeX_mm: 1.6; SizeY_mm: 0.8; EIA_Code: E96; U/M: EA; AEC Category: Q200
TP1 TP5 TP6 TP8 = 5012: Test Point, Multipurpose, White, TH; Manufacturer: Keystone; CompType: Test Point Loop; ContactFinish: Silver
TP2 = 5002: Test Point, Miniature, White, TH; Manufacturer: Keystone; CompType: Test Point Loop; U/M: EA
TP3 TP4 = 1598-2: Terminal, Turret, TH, Triple; Manufacturer: Keystone; CompType: Turret Terminal; U/M: EA
TP7 = 5011: Test Point, Multipurpose, Black, TH; Manufacturer: Keystone; CompType: Test Point Loop; ContactFinish: Silver
U1 = TPS7A6650QDGNRQ1: High-Voltage Ultralow-Iq Low-Dropout Regulator, DGN0008D; Manufacturer: Texas Instruments; SymbolCreator: a0411947; SizeArea_mm2: 15.655; SizeAreaWB_mm2: 35.955; SizeX_mm: 5.05; SizeY_mm: 3.1; SizeZ_mm: 1.1; CompType: IC; U/M: EA
U2 = LM5141QRGEQ1: IC, PWM, Buck Controller, w/ Dither; Manufacturer: Texas Instruments; SymbolVersion: use current date i.e. 2008-05-20; SymbolCreator: Use a-id; U/M: EA, IN, or GM
ZX1-ZX3 = AssemblyNote: This Assembly Note will show in the PcbDoc and associated outputs; SymbolCreator: codlsc

## Sheet PMP20682-HW.SchDoc: LM5141 EVM HARDWARE
size 431 x 279 mm; Date: Not shown in title block; ApprovedBy: Not shown in title block; CheckedBy: Not shown in title block; Author: Not shown in title block; CompanyName: Not shown in title block; Engineer: Not shown in title block; Organization: Not shown in title block; Address1: Not shown in title block; Address2: Not shown in title block; Address3: Not shown in title block; Address4: Not shown in title block; DocumentNumber: 2; Revision: Use project parameter SCH_Rev; SheetNumber: 2; SheetTotal: 2; PageSetup: Record=PageOptions¦CenterHorizontal=True¦CenterVertical=True¦PrintScale=1.00¦XCorrection=1.00¦YCorrection=1.00¦PrintKind=0¦BorderSize=5000000¦LeftOffset=0¦BottomOffset=0¦Orientation=2¦PaperLength=1000¦PaperWidth=1000¦Scale=100¦PaperSource=15¦PrintQuality=600¦MediaType=1¦DitherType=10¦PaperKind=Letter¦PrintScaleMode=1
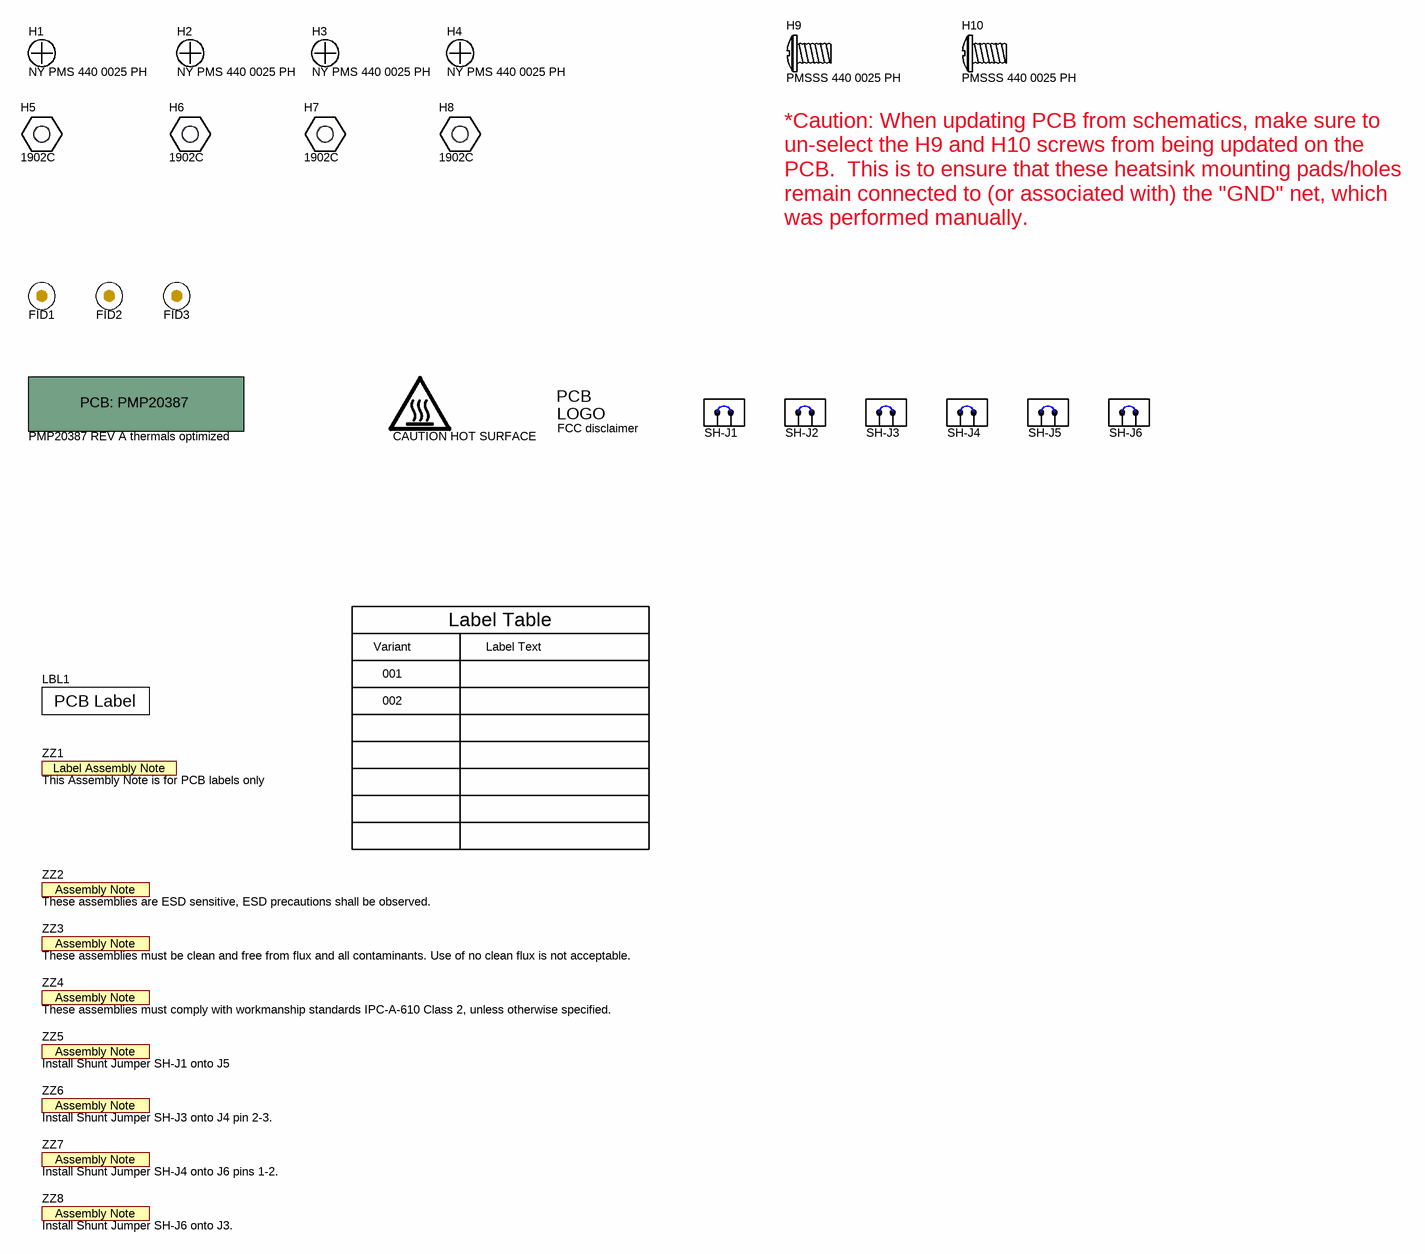
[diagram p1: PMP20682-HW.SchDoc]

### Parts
!PCB1  PMP20387 REV A thermals optimized  (mechanical)
FID1  Fiducial  [Fiducial10-20]  (value not drawn)
FID2  Fiducial  [Fiducial10-20]  (value not drawn)
FID3  Fiducial  [Fiducial10-20]  (value not drawn)
H1  NY PMS 440 0025 PH  [NY PMS 440 0025 PH]
H2  NY PMS 440 0025 PH  [NY PMS 440 0025 PH]
H3  NY PMS 440 0025 PH  [NY PMS 440 0025 PH]
H4  NY PMS 440 0025 PH  [NY PMS 440 0025 PH]
H5  1902C  [Keystone_1902C]
H6  1902C  [Keystone_1902C]
H7  1902C  [Keystone_1902C]
H8  1902C  [Keystone_1902C]
H9  PMSSS 440 0025 PH  [B_F_PMSSS4400025PH]
H10  PMSSS 440 0025 PH  [B_F_PMSSS4400025PH]
LBL1  (no value)  [Label_650x200]
Logo1  FCC disclaimer  [FCC_disclaimer]  (no BOM)
Logo2  CAUTION HOT SURFACE  [IEC_HotSurface_Small]  (no BOM)
SH-J1  60900213421  [Wurth_60900213421]  (value not drawn)  (mechanical)
SH-J2  60900213421  [Wurth_60900213421]  (value not drawn)  (mechanical)
SH-J3  60900213421  [Wurth_60900213421]  (value not drawn)  (mechanical)
SH-J4  60900213421  [Wurth_60900213421]  (value not drawn)  (mechanical)
SH-J5  60900213421  [Wurth_60900213421]  (value not drawn)  (mechanical)
SH-J6  60900213421  [Wurth_60900213421]  (value not drawn)  (mechanical)
ZZ1  This Assembly Note is for PCB labels only  [AssemblyNoteLabel]  (no BOM)
ZZ2  These assemblies are ESD sensitive, ESD precautions shall be observed.  [AssemblyNote]  (no BOM)
ZZ3  These assemblies must be clean and free from flux and all contaminants. Use of no clean flux is not acceptable.  [AssemblyNote]  (no BOM)
ZZ4  These assemblies must comply with workmanship standards IPC-A-610 Class 2, unless otherwise specified.  [AssemblyNote]  (no BOM)
ZZ5  Install Shunt Jumper SH-J1 onto J5  [AssemblyNote]  (no BOM)
ZZ6  Install Shunt Jumper SH-J3 onto J4 pin 2-3.  [AssemblyNote]  (no BOM)
ZZ7  Install Shunt Jumper SH-J4 onto J6 pins 1-2.  [AssemblyNote]  (no BOM)
ZZ8  Install Shunt Jumper SH-J6 onto J3.  [AssemblyNote]  (no BOM)

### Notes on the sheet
- *Caution: When updating PCB from schematics, make sure to un-select the H9 and H10 screws from being updated on the PCB.  This is to ensure that these heatsink mounting pads/holes remain connected to (or associated with) the "GND" net, which was performed manually.
- Variant
- Label Table
- Label Text
- 001
- 002

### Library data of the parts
!PCB1 = PCB_OtherProject: Manufacturer: Any; SymbolCreator: a0412235; CompType: PCB; U/M: EA
FID1-FID3 = Fiducial: Fiducial mark.  There is nothing to buy or mount.; SymbolCreator: codlsc
H1-H4 = NY PMS 440 0025 PH: Machine Screw, Round, #4-40 x 1/4, Nylon, Philips panhead; Manufacturer: B&F Fastener Supply; CompType: Hardware; SymbolCreator: codlsc; U/M: EA
H5-H8 = 1902C: Standoff, Hex, 0.5"L #4-40 Nylon; Manufacturer: Keystone; CompType: Hardware
H9 H10 = PMSSS 440 0025 PH: MACHINE SCREW PAN PHILLIPS 4-40; Manufacturer: B&F Fastener Supply; SymbolCreator: a0412235; CompType: Standoff
LBL1 = THT-14-423-10: Thermal Transfer Printable Labels, 0.650" W x 0.200" H - 10,000 per roll; Manufacturer: Brady; SymbolCreator: a0412235; CompType: Label
Logo1 = FCC_disclaimer: SymbolCreator: codlsc
Logo2 = IEC_HotSurface: IEC 61010-1 Hot Surface Warning; SymbolCreator: a0412235
SH-J1-SH-J6 = 60900213421: Shunt, 2.54mm, Gold, Black; Manufacturer: Wurth Elektronik
ZZ1 = AssemblyNoteLabel: SymbolCreator: a0412235
ZZ2-ZZ8 = AssemblyNote: SymbolCreator: codlsc

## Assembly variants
001: not fitted C2 C3 C13 C18 C19 C22 C34 D1 FID1 FID2 FID3 L4 R1 R3 R5 R13 R21 R22 R23 U1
